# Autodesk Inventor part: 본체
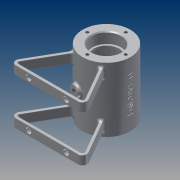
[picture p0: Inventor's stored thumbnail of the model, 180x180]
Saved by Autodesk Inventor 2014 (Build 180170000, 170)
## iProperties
Created: 2016-03
Part Number: 본체
Material: 알루미늄 6061
Document SubType Name: Modeling
Designer: 406-12
Mass: 210.689 g
Surface Area: 327.804 cm^2
Volume: 77.7452 cm^3
Density: 2.71 g/cm^3
Appearance: 알루미늄 - 평지
Author: 406-12
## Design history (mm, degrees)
sketch "스케치1"
  geometry: C1 r 26 at (0, 0); 1 further point
  constraints: 1 centre point, 1 coincident
  dimensions: "d0" = 52 diameter of C1
extrude "돌출1" new body sketch "스케치1" stored distance "d1" = 70; taper "d2" = 0 deg
node "작업 평면1"
sketch "스케치2"
  geometry: C1 r 5 at (0, 0); 1 further point
  constraints: 1 centre point, 1 coincident
  dimensions: "d4" = 10 diameter of C1
extrude "돌출2" join sketch "스케치2" stored distance "d5" = 70; taper "d6" = 0 deg
sketch "스케치3"
  geometry: C1 r 5 at (0, 0) reference; 1 further point
  constraints: 1 coincident
hole "구멍1" sketch "스케치3" at (0, 0) diameter "d7" = 5.188; stored, may be unused: countersink angle "d11" = 90 deg, drill point angle "d13" = 118 deg; dims "d8" = 15, "d9" = 4, "d10" = 2, "d12" = 20
fillet "모깎기1" dims "d14" = 2
node "작업 평면3"
sketch "스케치6"
  geometry: C1 r 6 at (0, 0); 1 further point
  constraints: 1 centre point, 1 coincident
  dimensions: "d22" = 12 diameter of C1
extrude "돌출3" join sketch "스케치6" stored distance "d23" = 3; taper "d24" = 0 deg
sketch "스케치7"
  geometry: C1 r 6 at (0, 0) reference; 1 further point
  constraints: 1 coincident
hole "구멍2" sketch "스케치7" at (0, 0) diameter "d25" = 5.188; stored, may be unused: countersink angle "d29" = 90 deg, drill point angle "d31" = 118 deg; dims "d26" = 15, "d27" = 4, "d28" = 2, "d30" = 20
node "작업 평면6"
sketch "스케치8"
  geometry: L1 (0, 32.549)-(0, -51.927); L2 (-38.119, 0)-(37.3, 0); L3 (-15.852, -18.681)-(-38.264, -57.5); L4 (-33.934, -65)-(33.934, -65); L5 (15.852, -18.681)-(38.264, -57.5); L6 (13.432, -20.49)-(35.666, -59); L7 (33.934, -62)-(-33.934, -62); L8 (-35.666, -59)-(-13.432, -20.49); C1 r 26 at (0, 0) reference; A1 r 5 centre (-33.934, -60) between (-38.264, -57.5) and (-33.934, -65); A2 r 24.5 centre (0, 0) between (-15.852, -18.681) and (-13.432, -20.49); A3 r 24.5 centre (0, 0) between (13.432, -20.49) and (15.852, -18.681); A4 r 5 centre (33.934, -60) between (33.934, -65) and (38.264, -57.5); A5 r 2 centre (33.934, -60) between (33.934, -62) and (35.666, -59); A6 r 2 centre (-33.934, -60) between (-35.666, -59) and (-33.934, -62); 2 further points
  constraints: 16 end point, 12 point on circle, 6 centre point, 4 symmetric about line, 4 tangent, 1 coincident, 1 horizontal, 1 parallel, 1 point on line, 1 vertical, 3 other
  dimensions: "d34" = 0 distance from line of point (0, 0) L1; "d35" = 0 distance from line of point (0, 0) L2; "d44" = 5 radius of A1; "d116" = 24.5 radius of A2; "d117" = 24.5 radius of A3; "d128" = 30 deg angle of L3 L1; "d130" = 3 distance between parallel lines of L3 L8; "d131" = 16.63749 distance from line of point (0, -24.5) L5; "d134" = 62 distance between parallel lines of L2 L7; "d135" = 27.91524 distance from line of L2.end L5; "d136" = 11.88709 distance from line of L1.start L5; "d138" = 37.39961 distance from line of L2.start L5
extrude "돌출4" join sketch "스케치8" distance "d51" = 10; taper "d52" = 0 deg
sketch "스케치9"
  geometry: L1 (26, 35)-(-26, 35) reference; L2 (-26, -35)-(26, -35) reference; L3 (0, 35)-(0, -35); L4 (0, 35)-(16, 35); L5 (16, 35)-(16, 23.3); L6 (15.7, 23)-(14, 23); L7 (14, 23)-(14, 21); L8 (14, 21)-(18, 21); L9 (21, 18)-(21, -18); L10 (18, -21)-(14, -21); L11 (0, -35)-(16, -35); L12 (16, -35)-(16, -23.3); L13 (15.7, -23)-(14, -23); L14 (14, -23)-(14, -21); A1 r 0.3 centre (15.7, 23.3) between (15.7, 23) and (16, 23.3); A2 r 0.3 centre (15.7, -23.3) between (16, -23.3) and (15.7, -23); A3 r 3 centre (18, -18) between (18, -21) and (21, -18); A4 r 3 centre (18, 18) between (21, 18) and (18, 21); 1 further point
  constraints: 24 end point, 9 tangent, 8 point on circle, 7 parallel, 4 centre point, 2 equal radius, 2 midpoint, 2 point on line, 1 vertical
  dimensions: "d53" = 0.3 radius of A1; "d54" = 3 radius of A3; "d55" = 90 deg angle of L5 L1; "d56" = 90 deg angle of L7 L1; "d57" = 12 distance between parallel lines of L6 L1; "d58" = 58 distance between parallel lines of L13 L1; "d59" = 14 distance between parallel lines of L8 L1; "d60" = 56 distance between parallel lines of L10 L1; "d61" = 5 distance between parallel lines of L12 L9; "d62" = 7 distance between parallel lines of L14 L9; "d63" = 21 distance between parallel lines of L9 L3; "d64" = 5 distance from line of L1.start L9; "d65" = 12 distance from line of L1.start L7
revolve "회전1" sketch "스케치9" stored, may be unused: angle "d66" = 90 deg
chamfer "모따기1" distance "d67" = 1; stored, may be unused: second distance "d68" = 2, angle "d69" = 45 deg
sketch "스케치10"
  geometry: L1 (0, 0)-(0, 21); C1 r 26 at (0, 0) reference; C2 r 17 at (0, 0) reference; 4 further points
  constraints: 2 end point, 1 coincident, 1 vertical, 5 other
  dimensions: "d70" = 21 distance of C1.centre L1.end; "d73" = 360 deg dimension on C1.centre point (0, 21) (derived)
hole "구멍3" sketch "스케치10" at (0, 21), (-21, 0), (0, -21), (21, 0) diameter "d75" = 3.242; stored, may be unused: countersink angle "d79" = 90 deg, drill point angle "d81" = 118 deg; dims "d76" = 8, "d77" = 4, "d78" = 2, "d80" = 10
sketch "스케치11"
  geometry: L1 (0, 0)-(0, 21); C1 r 26 at (0, 0) reference; C2 r 17 at (0, 0) reference; 4 further points
  constraints: 2 end point, 1 coincident, 1 vertical, 5 other
  dimensions: "d82" = 21 distance of C1.centre L1.end; "d85" = 360 deg dimension on C1.centre point (0, 21) (derived)
hole "구멍4" sketch "스케치11" at (0, 21), (-21, 0), (0, -21), (21, 0) diameter "d87" = 3.242; stored, may be unused: countersink angle "d91" = 90 deg, drill point angle "d93" = 118 deg; dims "d88" = 8, "d89" = 4, "d90" = 2, "d92" = 10
node "작업 평면7"
sketch "스케치12"
  geometry: 2 further points
  constraints: 1 other
feature "엠보싱1" sketch "스케치12" dims "d95" = 0.5, "d96" = 0
fillet "모깎기2" dims "d109" = 0.5
fillet "모깎기3" dims "d110" = 3
fillet "모깎기4" dims "d113" = 2
sketch "스케치15"
  geometry: L1 (67.868, -10)-(0, -10) reference; L2 (67.868, 0)-(67.868, -10) reference; L3 (0, 50)-(67.868, 50) reference; C1 r 3 at (13.934, 45); C2 r 3 at (54.883, 45); C3 r 3 at (13.934, -5); C4 r 3 at (54.883, -5); 1 further point
  constraints: 4 centre point, 3 equal radius
  dimensions: "d141" = 5 distance from line of C1.centre L3; "d142" = 5 distance from line of C2.centre L3; "d143" = 20 horizontal distance of C1.centre point (33.934, 20); "d144" = 6 diameter of C2; "d145" = 12.98453 distance from line of C2.centre L2; "d146" = 12.98453 distance from line of C4.centre L2; "d147" = 5 distance from line of C4.centre L1; "d148" = 53.93376 distance from line of C3.centre L2; "d149" = 5 distance from line of C3.centre L1
extrude "돌출6" cut sketch "스케치15" distance "d150" = 10; taper "d151" = 0 deg
node "솔리드1"
mirror "대칭1"
node "투영된 루프1"
other parameters: "d3" = 29, "d46" = 49, "d94" = 26
